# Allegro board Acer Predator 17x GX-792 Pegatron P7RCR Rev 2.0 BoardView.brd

Outline 324.5 x 193.7 mm; copper layers: TOP, GND1, IN1, GND2, IN2, GND3, VCC1, VCC2, GND4, IN3, GND5, IN4, GND6, BOTTOM. Coordinates in mm from the lower left corner of the outline.
Outline path: 0,81.74 arc(0.23,82.38) 0.82,82.72 0.83,82.72 arc(28.27,98.66) 39.1,128.49 39.1,132.99 arc(39.39,133.7) 40.1,133.99 43.1,133.99 arc(50.1,140.99) 43.1,147.99 40.1,147.99 arc(39.39,148.28) 39.1,148.99 39.1,192.7 arc(39.39,193.41) 40.1,193.7 78,193.7 arc(78.35,193.55) 78.5,193.2 arc(78.65,192.85) 79,192.7 98,192.7 arc(98.35,192.85) 98.5,193.2 arc(98.65,193.55) 99,193.7 210.2,193.7 arc(210.55,193.55) 210.7,193.2 210.7,191.9 arc(210.85,191.55) 211.2,191.4 211.5,191.4 arc(211.85,191.25) 212,190.9 212,126.77 arc(212,126.71) 212.01,126.64 arc(213.65,119.89) 216.47,113.55 arc(216.57,112.86) 216.2,112.27 214.01,110.61 arc(213.19,104.65) 219.14,103.84 221.28,105.46 arc(221.95,105.66) 222.59,105.36 arc(224.49,103.56) 226.51,101.88 arc(235.15,96.93) 244.81,94.49 arc(245.3,94.25) 245.59,93.79 246.2,91.79 arc(246.53,91.3) 247.09,91.09 arc(251.6,91.05) 256.08,91.56 arc(256.67,91.91) 256.9,92.55 256.9,94.36 arc(257.09,94.95) 257.59,95.31 arc(267.25,99.2) 275.42,105.65 arc(281.79,116.35) 284,128.6 284,135.3 arc(284.29,136.01) 285,136.3 287,136.3 arc(292,141.3) 287,146.3 285,146.3 arc(284.29,146.59) 284,147.3 284,165.9 arc(284.29,166.61) 285,166.9 293.5,166.9 arc(293.85,167.05) 294,167.4 294,167.9 arc(294.29,168.61) 295,168.9 321,168.9 arc(321.35,168.75) 321.5,168.4 321.5,158.7 arc(321.65,158.35) 322,158.2 322.15,158.2 arc(322.5,158.05) 322.65,157.7 322.65,154.7 arc(322.5,154.35) 322.15,154.2 313.85,154.2 arc(313,154.55) 313.35,153.7 313.35,138.1 arc(313,137.25) 313.85,137.6 322.15,137.6 arc(322.5,137.45) 322.65,137.1 322.65,133.1 arc(322.5,132.75) 322.15,132.6 315.04,132.6 arc(314.19,132.95) 314.54,132.1 314.54,115.8 arc(314.19,114.95) 315.04,115.3 322.15,115.3 arc(322.5,115.15) 322.65,114.8 322.65,109.15 arc(322.5,108.8) 322.15,108.65 315.75,108.65 arc(315.25,108.15) 315.75,107.65 315.75,94.05 arc(315.25,93.55) 315.75,93.05 322.15,93.05 arc(322.5,92.9) 322.65,92.55 322.65,87.35 arc(322.5,87) 322.15,86.85 321.9,86.85 arc(321.75,86.5) 321.4,86.35 315.25,86.35 arc(314.75,86.85) 314.25,86.35 314.25,72.85 arc(314.75,72.35) 315.25,72.85 321.4,72.85 arc(321.75,72.7) 321.9,72.35 321.9,59.45 arc(321.75,59.1) 321.4,58.95 315.25,58.95 arc(314.75,59.45) 314.25,58.95 314.25,45.45 arc(314.75,44.95) 315.25,45.45 321.4,45.45 arc(321.75,45.3) 321.9,44.95 321.9,40.45 arc(322.05,40.1) 322.4,39.95 324,39.95 arc(324.35,39.8) 324.5,39.45 324.5,17.9 arc(324.21,17.19) 323.5,16.9 316,16.9 arc(315.29,16.61) 315,15.9 315,12.9 arc(314.71,12.19) 314,11.9 243.5,11.9 arc(243.15,11.75) 243,11.4 243,7.3 arc(242.71,6.59) 242,6.3 179.1,6.3 arc(178.39,6.59) 178.1,7.3 178.1,7.5 arc(177.81,8.21) 177.1,8.5 162.5,8.5 arc(161.79,8.21) 161.5,7.5 161.5,1 arc(161.21,0.29) 160.5,0 67.2,0 arc(66.49,0.29) 66.2,1 66.2,7 arc(65.91,7.71) 65.2,8 55.3,8 arc(54.59,7.71) 54.3,7 54.3,5.5 arc(54.01,4.79) 53.3,4.5 1,4.5 arc(0.29,4.79) 0,5.5 0,81.74 ; 214,193.2 arc(214.15,193.55) 214.5,193.7 259.5,193.7 arc(259.85,193.55) 260,193.2 260,185.7 arc(259.85,185.35) 259.5,185.2 214.5,185.2 arc(214.15,185.35) 214,185.7 214,193.2

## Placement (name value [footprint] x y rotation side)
C0501  0.022UF/16V  [VX_C0402_SMALL]  68.31 101.84 180 top
C0502  0.022UF/16V  [VX_C0402_SMALL]  64.12 102.34 270 top
C0600  0.22UF/16V  [VX_C0402_SMALL]  128.25 117.13 180 top
C0601  0.22UF/16V  [VX_C0402_SMALL]  126.57 116.06 180 top
C0602  0.22UF/16V  [VX_C0402_SMALL]  126.57 115.17 180 top
C0603  0.22UF/16V  [VX_C0402_SMALL]  128.23 113.75 180 top
C0604  0.22UF/16V  [VX_C0402_SMALL]  126.55 113.57 180 top
C0605  0.22UF/16V  [VX_C0402_SMALL]  128.33 112.25 180 top
C0606  0.22UF/16V  [VX_C0402_SMALL]  126.6 111.13 180 top
C0607  0.22UF/16V  [VX_C0402_SMALL]  128.25 116.24 180 top
C0608  0.22UF/16V  [VX_C0402_SMALL]  128.23 114.64 180 top
C0609  0.22UF/16V  [VX_C0402_SMALL]  126.55 112.68 180 top
C0610  0.22UF/16V  [VX_C0402_SMALL]  128.33 111.36 180 top
C0611  0.22UF/16V  [VX_C0402_SMALL]  126.6 110.24 180 top
C0612  0.22UF/16V  [VX_C0402_SMALL]  128.2 108.34 180 top
C0613  0.22UF/16V  [VX_C0402_SMALL]  128.2 109.23 180 top
C0614  0.22UF/16V  [VX_C0402_SMALL]  126.55 107.3 180 top
C0615  0.22UF/16V  [VX_C0402_SMALL]  126.55 108.19 180 top
C0616  0.22UF/16V  [VX_C0402_SMALL]  126.37 106.41 180 top
C0617  0.22UF/16V  [VX_C0402_SMALL]  126.37 105.52 180 top
C0618  0.22UF/16V  [VX_C0402_SMALL]  128.56 104.35 180 top
C0619  0.22UF/16V  [VX_C0402_SMALL]  128.56 105.24 180 top
C0620  0.22UF/16V  [VX_C0402_SMALL]  126.37 104.22 180 top
C0621  0.22UF/16V  [VX_C0402_SMALL]  126.37 103.33 180 top
C0622  0.22UF/16V  [VX_C0402_SMALL]  128.05 102.29 180 top
C0623  0.22UF/16V  [VX_C0402_SMALL]  128.05 103.18 180 top
C0624  0.22UF/16V  [VX_C0402_SMALL]  126.35 102.14 180 top
C0625  0.22UF/16V  [VX_C0402_SMALL]  126.35 101.25 180 top
C0626  0.22UF/16V  [VX_C0402_SMALL]  128.05 100.16 180 top
C0627  0.22UF/16V  [VX_C0402_SMALL]  128.05 101.05 180 top
C0628  0.22UF/16V  [VX_C0402_SMALL]  126.35 100.01 180 top
C0629  0.22UF/16V  [VX_C0402_SMALL]  126.35 99.12 180 top
C0630  0.22UF/16V  [VX_C0402_SMALL]  128.05 97.9 180 top
C0631  0.22UF/16V  [VX_C0402_SMALL]  128.05 98.79 180 top
C0701  0.1UF/6.3V  [VX_C0402_SMALL]  69.56 105.42 90 bottom
C0702  0.1UF/6.3V  [VX_C0402_SMALL]  122.15 79.48 0 bottom
C0703  0.1UF/6.3V  [VX_C0402_SMALL]  147.3 27.41 270 bottom
C0900  1UF/6.3V  [VX_C0201_H14]  100.22 127.67 180 top
C0901  1UF/6.3V  [VX_C0201_H14]  97.68 112.3 180 top
C0902  1UF/6.3V  [VX_C0201_H14]  102.89 122.03 180 top
C0903  1UF/6.3V  [VX_C0201_H14]  102.89 123.55 180 top
C0904  1UF/6.3V  [VX_C0201_H14]  97.43 124.19 180 top
C0905  1UF/6.3V  [VX_C0201_H14]  100.22 122.03 0 top
C0906  1UF/6.3V  [VX_C0201_H14]  100.22 123.55 0 top
C0907  1UF/6.3V  [VX_C0201_H14]  106.32 116.09 0 top
C0908  1UF/6.3V  [VX_C0201_H14]  104.92 125.89 180 top
C0909  1UF/6.3V  [VX_C0201_H14]  104.79 112.3 180 top
C0910  1UF/6.3V  [VX_C0201_H14]  97.68 113.06 180 top
C0911  1UF/6.3V  [VX_C0201_H14]  107.97 114.15 180 top
C0912  1UF/6.3V  [VX_C0201_H14]  97.68 116.09 180 top
C0913  1UF/6.3V  [VX_C0201_H14]  107.97 113.39 180 top
C0914  1UF/6.3V  [VX_C0201_H14]  101.36 113.82 180 top
C0915  1UF/6.3V  [VX_C0201_H14]  106.19 122.79 0 top
C0916  1UF/6.3V  [VX_C0201_H14]  100.22 122.79 0 top
C0917  1UF/6.3V  [VX_C0201_H14]  102.89 124.32 180 top
C0918  1UF/6.3V  [VX_C0201_H14]  100.22 124.32 0 top
C0919  1UF/6.3V  [VX_C0201_H14]  99.84 112.3 0 top
C0920  1UF/6.3V  [VX_C0201_H14]  102.53 127.67 180 top
C0921  1UF/6.3V  [VX_C0201_H14]  97.68 113.82 180 top
C0922  1UF/6.3V  [VX_C0201_H14]  101.36 115.35 180 top
C0923  1UF/6.3V  [VX_C0201_H14]  101.36 114.59 180 top
C0924  1UF/6.3V  [VX_C0201_H14]  101.36 113.06 180 top
C0925  1UF/6.3V  [VX_C0201_H14]  103.27 113.82 0 top
C0926  1UF/6.3V  [VX_C0201_H14]  103.27 113.06 0 top
C0927  1UF/6.3V  [VX_C0201_H14]  104.79 115.35 180 top
C0928  1UF/6.3V  [VX_C0201_H14]  99.84 114.59 0 top
C0929  1UF/6.3V  [VX_C0201_H14]  97.81 125.76 180 top
C0930  1UF/6.3V  [VX_C0201_H14]  95.39 124.44 270 top
C0931  1UF/6.3V  [VX_C0201_H14]  97.43 121.9 180 top
C0932  1UF/6.3V  [VX_C0201_H14]  97.43 122.67 180 top
C0933  1UF/6.3V  [VX_C0201_H14]  106.32 113.06 0 top
C0934  1UF/6.3V  [VX_C0201_H14]  106.32 113.82 0 top
C0935  1UF/6.3V  [VX_C0201_H14]  106.32 112.3 0 top
C0936  1UF/6.3V  [VX_C0201_H14]  106.32 114.59 0 top
C0937  1UF/6.3V  [VX_C0201_H14]  99.84 115.35 0 top
C0938  1UF/6.3V  [VX_C0201_H14]  97.81 127.67 180 top
C0939  1UF/6.3V  [VX_C0201_H14]  96.16 124.44 270 top
C0940  1UF/6.3V  [VX_C0201_H14]  106.19 123.55 0 top
C0941  1UF/6.3V  [VX_C0201_H14]  106.19 124.32 0 top
C0942  1UF/6.3V  [VX_C0201_H14]  104.79 113.06 180 top
C0943  1UF/6.3V  [VX_C0201_H14]  104.79 113.82 180 top
C0944  1UF/6.3V  [VX_C0201_H14]  104.79 114.59 180 top
C0945  1UF/6.3V  [VX_C0201_H14]  102.89 122.79 180 top
C0946  1UF/6.3V  [VX_C0201_H14]  100.22 125.89 180 top
C0947  1UF/6.3V  [VX_C0201_H14]  103.27 112.3 0 top
C0948  1UF/6.3V  [VX_C0201_H14]  99.84 113.82 0 top
C0949  1UF/6.3V  [VX_C0201_H14]  99.84 113.06 0 top
C0950  1UF/6.3V  [VX_C0201_H14]  97.68 114.59 180 top
C0951  1UF/6.3V  [VX_C0201_H14]  97.68 115.35 180 top
C0952  1UF/6.3V  [VX_C0201_H14]  103.27 115.35 0 top
C0953  1UF/6.3V  [VX_C0201_H14]  103.27 114.59 0 top
C0954  1UF/6.3V  [VX_C0201_H14]  106.32 115.35 0 top
C0955  1UF/6.3V  [VX_C0201_H14]  102.53 125.89 180 top
C0956  1UF/6.3V  [VX_C0201_H14]  104.92 127.67 180 top
C0957  1UF/6.3V  [VX_C0201_H14]  97.43 123.43 180 top
C0958  1UF/6.3V  [VX_C0201_H14]  99.84 116.09 0 top
C0959  1UF/6.3V  [VX_C0201_H14]  106.19 122.03 0 top
C0960  1UF/6.3V  [VX_C0201_H14]  107.97 112.63 180 top
C0961  1UF/6.3V  [VX_C0201_H14]  107.97 114.92 180 top
C0962  1UF/6.3V  [VX_C0201_H14]  101.36 112.3 180 top
C0963  1UF/6.3V  [VX_C0201_H14]  89.04 114.43 180 top
C0964  1UF/6.3V  [VX_C0201_H14]  91.08 112.86 0 top
C0965  1UF/6.3V  [VX_C0201_H14]  93.62 112.93 0 top
C0966  1UF/6.3V  [VX_C0201_H14]  91.84 122.71 180 top
C0967  1UF/6.3V  [VX_C0201_H14]  86.25 114.41 0 top
C0968  1UF/6.3V  [VX_C0201_H14]  82.82 124.24 180 top
C0969  1UF/6.3V  [VX_C0201_H14]  87.14 121.95 180 top
C0970  1UF/6.3V  [VX_C0201_H14]  85.62 124.24 0 top
C0971  1UF/6.3V  [VX_C0201_H14]  83.46 112.81 180 top
C0972  1UF/6.3V  [VX_C0201_H14]  93.62 115.22 0 top
C0973  1UF/6.3V  [VX_C0201_H14]  85.62 120.43 0 top
C0974  1UF/6.3V  [VX_C0201_H14]  90.31 124.24 0 top
C0975  1UF/6.3V  [VX_C0201_H14]  85.62 123.48 0 top
C0976  1UF/6.3V  [VX_C0201_H14]  87.14 124.24 180 top
C0977  1UF/6.3V  [VX_C0201_H14]  93.11 125.76 0 top
C0978  1UF/6.3V  [VX_C0201_H14]  91.84 120.43 180 top
C0979  1UF/6.3V  [VX_C0201_H14]  81.3 121.19 0 top
C0980  1UF/6.3V  [VX_C0201_H14]  87.14 120.43 180 top
C0981  1UF/6.3V  [VX_C0201_H14]  83.46 114.33 180 top
C0982  1UF/6.3V  [VX_C0201_H14]  83.46 115.09 180 top
C0983  1UF/6.3V  [VX_C0201_H14]  82.82 120.43 180 top
C0984  1UF/6.3V  [VX_C0201_H14]  91.84 121.19 180 top
C0985  1UF/6.3V  [VX_C0201_H14]  90.31 120.43 0 top
C0986  1UF/6.3V  [VX_C0201_H14]  81.3 125.76 180 top
C0987  1UF/6.3V  [VX_C0201_H14]  83.71 125.76 0 top
C0988  1UF/6.3V  [VX_C0201_H14]  82.82 122.71 180 top
C0989  1UF/6.3V  [VX_C0201_H14]  82.82 121.95 180 top
C0990  1UF/6.3V  [VX_C0201_H14]  82.82 123.48 180 top
C0991  1UF/6.3V  [VX_C0201_H14]  87.14 122.71 180 top
C0992  1UF/6.3V  [VX_C0201_H14]  89.04 115.17 180 top
C0993  1UF/6.3V  [VX_C0201_H14]  91.08 113.62 0 top
C0994  1UF/6.3V  [VX_C0201_H14]  93.62 113.7 0 top
C0995  1UF/6.3V  [VX_C0201_H14]  91.84 123.48 180 top
C0996  1UF/6.3V  [VX_C0201_H14]  91.84 124.24 180 top
C0997  1UF/6.3V  [VX_C0201_H14]  81.3 124.24 0 top
C0998  1UF/6.3V  [VX_C0201_H14]  88.41 127.67 0 top
C0999  1UF/6.3V  [VX_C0201_H14]  83.71 127.67 0 top
C1000  22UF/6.3V  [VX_C0603_H39_SMALL]  121.04 104.35 0 bottom
C1001  1UF/6.3V  [VX_C0402_SMALL]  79.01 111.51 90 top
C1002  1UF/6.3V  [VX_C0402_SMALL]  80.89 110.93 0 top
C1003  4.7UF/10V  [VX_C0402_H26_SMALL]  110.38 124.36 180 top
C1004  1UF/6.3V  [VX_C0402_SMALL]  108.07 122.51 180 top
C1005  1UF/6.3V  [VX_C0402_SMALL]  108.07 121.62 180 top
C1006  4.7UF/10V  [VX_C0402_H26_SMALL]  110.38 123.48 180 top
C1007  10UF/6.3V  [VX_C0603_SMALL]  86.68 108.95 180 top
C1008  10UF/6.3V  [VX_C0603_SMALL]  105.07 103.54 270 top
C1009  10UF/6.3V  [VX_C0603_SMALL]  93.71 102.98 270 top
C1010  10UF/6.3V  [VX_C0603_SMALL]  100.22 103.54 270 top
C1011  10UF/6.3V  [VX_C0603_SMALL]  104.61 107.64 90 top
C1012  10UF/6.3V  [VX_C0603_SMALL]  99.08 107.6 90 top
C1013  10UF/6.3V  [VX_C0603_SMALL]  107.33 107.35 90 top
C1014  10UF/6.3V  [VX_C0603_SMALL]  86.25 107.43 180 top
C1015  10UF/6.3V  [VX_C0603_SMALL]  88.03 106.97 90 top
C1016  10UF/6.3V  [VX_C0603_SMALL]  109.84 105.52 270 top
C1017  1UF/6.3V  [VX_C0201_H14]  107.68 129.01 180 top
C1018  1UF/6.3V  [VX_C0201_H14]  107.68 129.78 180 top
C1019  1UF/6.3V  [VX_C0201_H14]  107.68 130.54 180 top
C1020  10UF/6.3V  [VX_C0402_H28_SMALL]  110.39 118.85 0 top
C1021  10UF/6.3V  [VX_C0402_H28_SMALL]  110.34 116.92 0 top
C1022  10UF/6.3V  [VX_C0402_H28_SMALL]  110.34 116.09 0 top
C1023  220UF/6.3V  [VX_C7343D_KEMET]  106.91 156.83 270 top
C1101  0.22UF/6.3V  [VX_C0201]  290.18 32.87 90 top
C1102  0.22UF/6.3V  [VX_C0201]  290.94 32.87 90 top
C1103  0.22UF/6.3V  [VX_C0201]  293.86 33.26 90 top
C1104  0.22UF/6.3V  [VX_C0201]  293.1 33.26 90 top
C1105  0.22UF/6.3V  [VX_C0201]  296.32 33.18 90 top
C1106  0.22UF/6.3V  [VX_C0201]  295.55 33.18 90 top
C1107  0.22UF/6.3V  [VX_C0201]  298.68 32.93 90 top
C1108  0.22UF/6.3V  [VX_C0201]  297.92 32.93 90 top
C1109  0.1UF/6.3V  [VX_C0201]  276.97 47.99 270 top
C1110  0.1UF/6.3V  [VX_C0201]  274.43 52.43 180 bottom
C1111  0.1UF/6.3V  [VX_C0201]  279.38 52.18 180 bottom
C1129  0.1UF/6.3V  [VX_C0402_SMALL]  273.67 59.09 90 top
C1130  22pF/50V  [VX_C0402_SMALL]  302.95 32.24 0 top
C1131  27PF/50V  [VX_C0402_SMALL]  300.41 32.24 180 top
C1132  0.22UF/6.3V  [VX_C0201]  303.51 39.04 0 top
C1133  0.22UF/6.3V  [VX_C0201]  303.51 38.33 0 top
C1134  0.22UF/6.3V  [VX_C0201]  303.51 36.8 0 top
C1135  0.22UF/6.3V  [VX_C0201]  303.51 37.51 0 top
C1136  0.1UF/6.3V  [VX_C0201]  286.85 38.5 0 bottom
C1137  0.1UF/6.3V  [VX_C0201]  286.85 39.21 0 bottom
C1138  0.1UF/6.3V  [VX_C0201]  284.82 44.43 0 top
C1139  0.1UF/6.3V  [VX_C0201]  284.82 43.72 0 top
C1140  0.1UF/6.3V  [VX_C0201]  285.09 42.96 0 top
C1141  0.1UF/6.3V  [VX_C0201]  285.09 42.25 0 top
C1142  0.1UF/6.3V  [VX_C0201]  285.15 41.49 0 top
C1143  0.1UF/6.3V  [VX_C0201]  285.15 40.78 0 top
C1144  0.1UF/6.3V  [VX_C0201]  285.24 39.99 0 top
C1145  0.1UF/6.3V  [VX_C0201]  285.24 39.28 0 top
C1146  0.1UF/6.3V  [VX_C0201]  286.87 40.04 0 bottom
C1147  0.1UF/6.3V  [VX_C0201]  286.87 40.75 0 bottom
C1148  1UF/6.3V  [VX_C0402_SMALL]  298.62 39.44 270 bottom
C1149  1UF/6.3V  [VX_C0402_SMALL]  298.61 41.04 90 bottom
C1150  1UF/6.3V  [VX_C0402_SMALL]  299.47 41.04 90 bottom
C1151  1UF/6.3V  [VX_C0402_SMALL]  301.97 38.37 270 bottom
C1152  1UF/6.3V  [VX_C0402_SMALL]  301.13 38.37 270 bottom
C1153  1UF/6.3V  [VX_C0402_SMALL]  302.83 38.37 270 bottom
C1154  1UF/6.3V  [VX_C0402_SMALL]  299.46 39.44 270 bottom
C1155  10UF/6.3V  [VX_C0603_SMALL]  302.49 45.7 90 top
C1156  10UF/6.3V  [VX_C0603_SMALL]  303.76 45.7 90 top
C1157  10UF/6.3V  [VX_C0603_SMALL]  305.03 45.7 90 top
C1158  10UF/6.3V  [VX_C0603_SMALL]  301.22 45.7 90 top
C1159  47uF/4V  [VX_C0805_H57_SMALL]  305.09 48.29 270 top
C1160  47uF/4V  [VX_C0805_H57_SMALL]  306.81 48.29 270 top
C1161  47uF/4V  [VX_C0805_H57_SMALL]  303.36 48.29 270 top
C1163  10UF/6.3V  [VX_C0603_SMALL]  300.13 34.06 0 bottom
C1164  10UF/6.3V  [VX_C0603_SMALL]  300.13 36.73 0 bottom
C1165  1UF/6.3V  [VX_C0201_H14]  296.16 39.89 180 bottom
C1166  1UF/6.3V  [VX_C0201_H14]  296.16 40.61 180 bottom
C1167  1UF/6.3V  [VX_C0201_H14]  293.86 42.91 180 bottom
C1168  1UF/6.3V  [VX_C0201_H14]  295.13 41.61 180 bottom
C1169  1UF/6.3V  [VX_C0201_H14]  290.56 41.76 0 bottom
C1170  1UF/6.3V  [VX_C0201_H14]  290.15 39.71 180 bottom
C1171  1UF/6.3V  [VX_C0201_H14]  291.8 41.76 180 bottom
C1172  1UF/6.3V  [VX_C0201_H14]  289.54 41.51 270 bottom
C1173  1UF/6.3V  [VX_C0201_H14]  295.13 42.35 180 bottom
C1174  1UF/6.3V  [VX_C0201_H14]  294.86 37.36 270 bottom
C1175  1UF/6.3V  [VX_C0201_H14]  294.86 40.64 90 bottom
C1176  1UF/6.3V  [VX_C0201_H14]  294.74 39.66 0 bottom
C1177  1UF/6.3V  [VX_C0201_H14]  294.75 36.02 0 bottom
C1178  1UF/6.3V  [VX_C0201_H14]  292.79 40.34 270 bottom
C1179  1UF/6.3V  [VX_C0201_H14]  293.12 41.64 0 bottom
C1180  1UF/6.3V  [VX_C0201_H14]  292.86 42.63 90 bottom
C1181  1UF/6.3V  [VX_C0201_H14]  292.92 39.1 90 bottom
C1182  1UF/6.3V  [VX_C0201_H14]  292.92 37.85 270 bottom
C1183  1UF/6.3V  [VX_C0201_H14]  294.86 38.66 270 bottom
C1184  1UF/6.3V  [VX_C0201_H14]  295.59 38.04 270 bottom
C1185  1UF/6.3V  [VX_C0201_H14]  292.08 45.19 90 bottom
C1186  1UF/6.3V  [VX_C0201_H14]  299.19 43.25 90 bottom
C1187  1UF/6.3V  [VX_C0201_H14]  294.12 40.8 90 bottom
C1188  1UF/6.3V  [VX_C0201_H14]  296.53 41.64 180 bottom
C1191  47uF/4V  [VX_C0805_H57_SMALL]  280.87 44.04 90 bottom
C1192  47uF/4V  [VX_C0805_H57_SMALL]  282.65 44.04 90 bottom
C1201  0.1UF/6.3V  [VX_C0402_SMALL]  297.08 75.52 180 top
C1202  10PF/50V  [VX_C0402_SMALL]  295.36 70.59 270 top
C1203  10UF/6.3V  [VX_C0603_SMALL]  295.38 52.99 270 top
C1204  1UF/6.3V  [VX_C0402_SMALL]  289.16 54.59 180 top
C1205  1UF/6.3V  [VX_C0402_SMALL]  296.4 52.81 270 top
C1206  10UF/6.3V  [VX_C0603_SMALL]  294.11 52.99 270 top
C1207  2.2UF/6.3V  [VX_C0603_SMALL]  298 52.41 0 top
C1208  2.2UF/6.3V  [VX_C0603_SMALL]  286.61 54.31 0 top
C1209  22UF/6.3V  [VX_C0603_H39_SMALL]  287.69 60.61 270 top
C1210  22UF/6.3V  [VX_C0603_H39_SMALL]  286.42 63.81 90 top
C1211  22UF/6.3V  [VX_C0603_H39_SMALL]  286.42 60.61 270 top
C1212  0.1UF/6.3V  [VX_C0402_SMALL]  288.78 60.61 270 top
C1217  4.7UF/6.3V  [VX_C0603_SMALL]  299.5 61.96 270 top
C1218  1UF/6.3V  [VX_C0402_SMALL]  298 62.12 90 top
C1219  0.1UF/6.3V  [VX_C0402_SMALL]  296.78 62.59 90 top
C1220  10PF/25V  [VX_C0201]  308.72 28.05 270 top
C1221  2.2UF/6.3V  [VX_C0603_SMALL]  286.61 52.81 0 top
C1222  10UF/6.3V  [VX_C0805_H57_SMALL]  307.45 28.43 270 top
C1223  220PF/50V  [VX_C0402_SMALL]  302.9 57.36 0 top
C1224  220PF/50V  [VX_C0402_SMALL]  302.44 59.42 0 top
C1225  0.47UF/6.3V  [VX_C0201]  317.73 32.32 180 bottom
C1226  0.47UF/6.3V  [VX_C0201]  317.73 34.37 180 bottom
C1227  0.47UF/6.3V  [VX_C0201]  317.73 31.6 180 bottom
C1228  0.47UF/6.3V  [VX_C0201]  317.73 33.65 180 bottom
C1229  0.22UF/6.3V  [VX_C0402_SMALL]  284.56 55.79 180 bottom
C1301  0.1UF/6.3V  [VX_C0402_SMALL]  299.83 87.87 90 bottom
C1302  10UF/6.3V  [VX_C0402_H28_SMALL]  300.72 87.87 90 bottom
C1303  0.1UF/6.3V  [VX_C0402_SMALL]  291.7 86.21 180 bottom
C1304  0.1UF/6.3V  [VX_C0402_SMALL]  291.7 85.2 180 bottom
C1305  0.1UF/6.3V  [VX_C0402_SMALL]  291.7 87.23 0 top
C1306  0.1UF/6.3V  [VX_C0402_SMALL]  291.7 82.15 0 top
C1307  0.1UF/6.3V  [VX_C0402_SMALL]  291.7 84.18 0 top
C1308  0.1UF/6.3V  [VX_C0402_SMALL]  291.7 81.13 0 top
C1309  0.1UF/6.3V  [VX_C0402_SMALL]  291.7 88.25 0 top
C1310  0.1UF/6.3V  [VX_C0402_SMALL]  291.7 80.12 0 top
C1311  0.1UF/6.3V  [VX_C0402_SMALL]  291.7 83.17 0 top
C1312  0.1UF/6.3V  [VX_C0402_SMALL]  291.7 85.2 0 top
C1313  0.1UF/6.3V  [VX_C0402_SMALL]  299.57 80.32 0 top
C1314  0.1UF/6.3V  [VX_C0402_SMALL]  287.51 85.45 0 bottom
C1315  10UF/6.3V  [VX_C0402_H28_SMALL]  295.13 87.87 90 bottom
C1316  0.1UF/6.3V  [VX_C0402_SMALL]  292.97 78.72 270 top
C1317  0.01UF/16V  [VX_C0402_SMALL]  298.56 78.72 270 top
C1318  0.1UF/6.3V  [VX_C0402_SMALL]  296.4 89.77 180 top
C1319  0.1UF/6.3V  [VX_C0402_SMALL]  294.24 78.72 270 top
C1320  0.1UF/6.3V  [VX_C0402_SMALL]  275.32 85.07 270 top
C1321  0.1UF/6.3V  [VX_C0402_SMALL]  281.16 85.58 270 top
C1322  10UF/6.3V  [VX_C0402_H28_SMALL]  293.77 87.28 90 top
C1323  10UF/6.3V  [VX_C0402_H28_SMALL]  272.8 84.84 180 top
C1324  10UF/6.3V  [VX_C0402_H28_SMALL]  272.8 85.68 180 top
C1401  0.1UF/6.3V  [VX_C0402_SMALL]  257.79 49.81 0 top
C1402  0.1UF/6.3V  [VX_C0402_SMALL]  257.79 46.13 0 top
C1403  0.1UF/6.3V  [VX_C0402_SMALL]  257.79 44.1 0 top
C1404  0.1UF/6.3V  [VX_C0402_SMALL]  257.79 43.08 0 top
C1405  0.1UF/6.3V  [VX_C0402_SMALL]  257.79 50.7 0 top
C1406  0.1UF/6.3V  [VX_C0402_SMALL]  257.79 42.07 0 top
C1407  0.1UF/6.3V  [VX_C0402_SMALL]  262.95 52.78 0 top
C1408  0.1UF/6.3V  [VX_C0402_SMALL]  262.95 53.83 0 top
C1409  0.1UF/6.3V  [VX_C0402_SMALL]  257.79 45.11 0 top
C1410  0.1UF/6.3V  [VX_C0402_SMALL]  257.79 47.1 0 top
C1411  2.2UF/6.3V  [VX_C0603_SMALL]  260.94 40.57 270 top
C1412  2.2UF/6.3V  [VX_C0603_SMALL]  259.34 51.82 90 top
C1413  0.1UF/6.3V  [VX_C0402_SMALL]  264.27 41.18 270 top
C1414  0.01UF/16V  [VX_C0402_SMALL]  259.57 41.05 90 top
C1501  0.01UF/16V  [VX_C0402_SMALL]  48.22 14.71 180 top
C1502  0.01UF/16V  [VX_C0402_SMALL]  48.22 15.96 180 top
C1503  0.01UF/16V  [VX_C0402_SMALL]  47.35 15.96 0 top
C1504  0.01UF/16V  [VX_C0402_SMALL]  35.01 11.54 180 top
C1505  0.01UF/16V  [VX_C0402_SMALL]  30.97 10.68 0 top
C1506  0.01UF/16V  [VX_C0402_SMALL]  30.97 11.92 0 top
C1507  0.01UF/16V  [VX_C0402_SMALL]  47.35 14.71 0 top
C1508  0.01UF/16V  [VX_C0402_SMALL]  47.35 12.48 0 top
C1509  0.01UF/16V  [VX_C0402_SMALL]  47.35 13.72 0 top
C1510  0.01UF/16V  [VX_C0402_SMALL]  30.97 12.81 0 top
C1511  0.01UF/16V  [VX_C0402_SMALL]  30.97 14.05 0 top
C1512  0.1UF/6.3V  [VX_C0402_SMALL]  45.19 17.25 180 bottom
C1513  0.1UF/6.3V  [VX_C0402_SMALL]  60.69 15.98 180 top
C1514  0.01UF/16V  [VX_C0402_SMALL]  30.11 10.68 180 top
C1515  0.01UF/16V  [VX_C0402_SMALL]  30.11 11.92 180 top
C1516  0.1UF/6.3V  [VX_C0402_SMALL]  45.42 15.55 90 top
C1517  0.1UF/6.3V  [VX_C0402_SMALL]  39.63 12 90 top
C1600  10PF/50V  [VX_C0402_SMALL]  104.5 69.45 180 bottom
C1601  10PF/50V  [VX_C0402_SMALL]  104.5 68.56 180 bottom
C1602  0.1UF/6.3V  [VX_C0402_SMALL]  66.86 71.46 0 bottom
C1603  0.1UF/6.3V  [VX_C0402_SMALL]  66.86 68.79 0 bottom
C1604  2.2UF/6.3V  [VX_C0402_H24_SMALL]  97.52 71.23 180 bottom
C1605  0.1UF/6.3V  [VX_C0402_SMALL]  98.79 69.58 0 bottom
C1606  10PF/50V  [VX_C0402_SMALL]  98.79 68.69 180 bottom
C1607  2.2UF/6.3V  [VX_C0402_H24_SMALL]  91.93 42.15 0 bottom
C1608  0.1UF/6.3V  [VX_C0402_SMALL]  99.42 42.15 0 bottom
C1609  10PF/50V  [VX_C0402_SMALL]  94.16 42.15 0 bottom
C1610  0.1UF/6.3V  [VX_C0402_SMALL]  79.36 69.22 180 bottom
C1612  10UF/6.3V  [VX_C0402_H28_SMALL]  85.4 70.06 0 bottom
C1613  0.1UF/6.3V  [VX_C0402_SMALL]  85.38 68.79 0 bottom
C1614  10UF/6.3V  [VX_C0402_H28_SMALL]  87.71 70.12 180 bottom
C1615  0.1UF/6.3V  [VX_C0402_SMALL]  87.54 68.79 180 bottom
C1616  10PF/50V  [VX_C0402_SMALL]  89.46 54.7 0 top
C1617  10PF/50V  [VX_C0402_SMALL]  99.16 54.7 180 top
C1618  10PF/50V  [VX_C0402_SMALL]  83.55 69.37 0 bottom
C1619  10PF/50V  [VX_C0402_SMALL]  75.16 68.73 180 bottom
C1620  10PF/50V  [VX_C0402_SMALL]  76.54 71.71 270 bottom
C1700  10PF/50V  [VX_C0402_SMALL]  114.41 51.56 0 bottom
C1701  10PF/50V  [VX_C0402_SMALL]  108.36 54.7 180 top
C1702  0.1UF/6.3V  [VX_C0402_SMALL]  66.86 70.57 0 bottom
C1703  0.1UF/6.3V  [VX_C0402_SMALL]  66.86 69.68 0 bottom
C1704  2.2UF/6.3V  [VX_C0402_H24_SMALL]  102.85 70.34 180 bottom
C1705  0.1UF/6.3V  [VX_C0402_SMALL]  102.85 68.56 0 bottom
C1706  10PF/50V  [VX_C0402_SMALL]  102.85 69.45 180 bottom
C1707  0.1UF/6.3V  [VX_C0402_SMALL]  116.68 49.07 0 top
C1708  2.2UF/6.3V  [VX_C0402_H24_SMALL]  116.68 49.94 180 top
C1709  10PF/50V  [VX_C0402_SMALL]  106.71 54.7 180 top
C1710  0.1UF/6.3V  [VX_C0402_SMALL]  59.26 68.76 270 bottom
C1712  1UF/6.3V  [VX_C0402_SMALL]  61.7 100.95 180 top
C1713  10UF/6.3V  [VX_C0402_H28_SMALL]  83.81 42.15 0 bottom
C1714  0.47UF/6.3V  [VX_C0402_SMALL]  61.7 100.06 180 top
C1715  10UF/6.3V  [VX_C0402_H28_SMALL]  61.45 103.74 180 top
C1717  10PF/50V  [VX_C0402_SMALL]  64.98 67.55 270 bottom
C1718  10PF/50V  [VX_C0402_SMALL]  80.12 42.15 0 bottom
C1719  10PF/50V  [VX_C0402_SMALL]  114.79 46.46 180 bottom
C1801  10UF/6.3V  [VX_C0402_H28_SMALL]  55.91 67.52 270 bottom
C1802  10UF/6.3V  [VX_C0402_H28_SMALL]  80.19 68 90 bottom
C1803  10UF/6.3V  [VX_C0402_H28_SMALL]  97.49 42.15 0 bottom
C1804  10UF/6.3V  [VX_C0402_H28_SMALL]  59.65 67.55 0 bottom
C1805  10UF/6.3V  [VX_C0402_H28_SMALL]  70.19 69.58 0 bottom
C1806  10UF/6.3V  [VX_C0402_H28_SMALL]  70.19 68.74 0 bottom
C1807  10UF/6.3V  [VX_C0402_H28_SMALL]  72.22 69.43 180 bottom
C1808  10UF/6.3V  [VX_C0402_H28_SMALL]  83.55 68.54 0 bottom
C1809  10UF/6.3V  [VX_C0402_H28_SMALL]  73.29 67.52 90 bottom
C1810  10UF/6.3V  [VX_C0402_H28_SMALL]  54.57 42.27 0 bottom
C1811  10UF/6.3V  [VX_C0402_H28_SMALL]  77.48 67.55 90 bottom
C1812  10UF/6.3V  [VX_C0402_H28_SMALL]  81.67 69.22 180 bottom
C1813  10UF/6.3V  [VX_C0402_H28_SMALL]  50.91 67.52 270 bottom
C1814  10UF/6.3V  [VX_C0402_H28_SMALL]  74.76 67.52 90 bottom
C1815  10UF/6.3V  [VX_C0402_H28_SMALL]  64.98 69.17 90 bottom
C1816  10UF/6.3V  [VX_C0402_H28_SMALL]  95.69 69.15 90 bottom
C1817  10UF/6.3V  [VX_C0402_H28_SMALL]  91.37 67.51 0 bottom
C1818  10UF/6.3V  [VX_C0402_H28_SMALL]  97.24 67.55 270 bottom
C1819  10UF/6.3V  [VX_C0402_H28_SMALL]  95.89 42.15 180 bottom
C1820  10UF/6.3V  [VX_C0402_H28_SMALL]  103 54.69 180 top
C1821  10UF/6.3V  [VX_C0402_H28_SMALL]  96.35 67.55 270 bottom
C1822  10UF/6.3V  [VX_C0402_H28_SMALL]  89.26 42.15 0 bottom
C1823  10UF/6.3V  [VX_C0402_H28_SMALL]  74.78 54.7 0 top
C1824  10UF/6.3V  [VX_C0402_H28_SMALL]  77.07 54.7 0 top
C1825  10UF/6.3V  [VX_C0402_H28_SMALL]  80.94 54.7 180 top
C1826  10UF/6.3V  [VX_C0402_H28_SMALL]  104.76 42.15 180 bottom
C1827  10UF/6.3V  [VX_C0402_H28_SMALL]  46.36 67.52 270 bottom
C1828  10UF/6.3V  [VX_C0402_H28_SMALL]  85.5 54.7 0 top
C1829  10UF/6.3V  [VX_C0402_H28_SMALL]  47.91 67.52 270 bottom
C1830  10UF/6.3V  [VX_C0402_H28_SMALL]  66.66 42.27 180 bottom
C1831  10UF/6.3V  [VX_C0402_H28_SMALL]  64.47 42.22 0 bottom
C1832  10UF/6.3V  [VX_C0402_H28_SMALL]  55.79 54.7 180 top
C1833  1UF/6.3V  [VX_C0402_SMALL]  50.12 54.7 180 top
C1834  1UF/6.3V  [VX_C0402_SMALL]  105.05 54.7 0 top
C1835  1UF/6.3V  [VX_C0402_SMALL]  93.69 54.7 180 top
C1836  1UF/6.3V  [VX_C0402_SMALL]  60.36 54.69 180 top
C1837  1UF/6.3V  [VX_C0402_SMALL]  44.99 54.7 180 top
C1838  1UF/6.3V  [VX_C0402_SMALL]  70.46 54.7 0 top
C1839  1UF/6.3V  [VX_C0402_SMALL]  66.83 54.7 0 top
C1840  1UF/6.3V  [VX_C0402_SMALL]  106.41 42.15 0 bottom
C1841  1UF/6.3V  [VX_C0402_SMALL]  69.96 42.27 180 bottom
C1842  1UF/6.3V  [VX_C0402_SMALL]  43.82 42.27 0 bottom
C1843  1UF/6.3V  [VX_C0402_SMALL]  52.78 54.68 0 top
C1844  1UF/6.3V  [VX_C0402_SMALL]  81.9 42.15 180 bottom
C1845  1UF/6.3V  [VX_C0402_SMALL]  62.87 42.22 180 bottom
C1846  1UF/6.3V  [VX_C0402_SMALL]  89.74 67.9 90 bottom
C1847  1UF/6.3V  [VX_C0402_SMALL]  96.98 69.17 90 bottom
C1848  1UF/6.3V  [VX_C0402_SMALL]  49.38 67.52 270 bottom
C1849  1UF/6.3V  [VX_C0402_SMALL]  52.97 42.27 180 bottom
C1850  1UF/6.3V  [VX_C0402_SMALL]  75.83 42.27 0 bottom
C1851  1UF/6.3V  [VX_C0402_SMALL]  74 42.27 180 bottom
C1852  1UF/6.3V  [VX_C0402_SMALL]  71.84 42.27 0 bottom
C1853  1UF/6.3V  [VX_C0402_SMALL]  68.36 42.27 0 bottom
C1854  1UF/6.3V  [VX_C0402_SMALL]  83.55 67.67 0 bottom
C1855  1UF/6.3V  [VX_C0402_SMALL]  71.84 68.21 90 bottom
C1856  1UF/6.3V  [VX_C0402_SMALL]  45.14 68.51 180 bottom
C1857  1UF/6.3V  [VX_C0402_SMALL]  81.08 68 90 bottom
C1858  1UF/6.3V  [VX_C0402_SMALL]  67.67 67.98 180 bottom
C1859  1UF/6.3V  [VX_C0402_SMALL]  57.51 67.52 270 bottom
C1860  1UF/6.3V  [VX_C0402_SMALL]  64.7 54.72 180 top
C1861  1UF/6.3V  [VX_C0402_SMALL]  67.67 67.14 180 bottom
C1862  1UF/6.3V  [VX_C0402_SMALL]  72.56 54.72 0 top
C1863  1UF/6.3V  [VX_C0402_SMALL]  58.15 54.72 0 top
C1864  1UF/6.3V  [VX_C0402_SMALL]  62.72 54.72 0 top
C1865  10UF/6.3V  [VX_C0402_H28_SMALL]  104.5 71.23 180 bottom
C1866  10UF/6.3V  [VX_C0402_H28_SMALL]  104.5 70.34 180 bottom
C1867  1UF/6.3V  [VX_C0402_SMALL]  104.59 72.12 180 bottom
C1868  1UF/6.3V  [VX_C0402_SMALL]  104.59 73.01 180 bottom
C1869  10UF/6.3V  [VX_C0402_H28_SMALL]  114.41 50.69 0 bottom
C1872  1UF/6.3V  [VX_C0402_SMALL]  114.41 49.85 0 bottom
C1880  1UF/6.3V  [VX_C0402_SMALL]  114 56.93 270 bottom
C1881  10UF/6.3V  [VX_C0402_H28_SMALL]  115.73 56.93 270 bottom
C1882  10UF/6.3V  [VX_C0402_H28_SMALL]  115.7 58.58 90 bottom
C1883  1UF/6.3V  [VX_C0402_SMALL]  114.87 58.58 90 bottom
C1886  10UF/6.3V  [VX_C0402_H28_SMALL]  109.96 54.69 0 top
C1888  1UF/6.3V  [VX_C0402_SMALL]  114.41 49.02 0 bottom
C1893  10UF/6.3V  [VX_C0402_H28_SMALL]  114.41 48.18 0 bottom
C1894  10UF/6.3V  [VX_C0402_H28_SMALL]  116.59 56.93 270 bottom
C1895  1UF/6.3V  [VX_C0402_SMALL]  114 58.58 90 bottom
C1896  1UF/6.3V  [VX_C0402_SMALL]  114.87 56.93 270 bottom
C1897  10UF/6.3V  [VX_C0402_H28_SMALL]  116.36 46.62 0 top
C1898  1UF/6.3V  [VX_C0402_SMALL]  116.36 45.78 0 top
C1899  10UF/6.3V  [VX_C0402_H28_SMALL]  116.36 44.94 0 top
C2000  0.22UF/6.3V  [VX_C0201]  209.84 54.36 0 bottom
C2001  0.22UF/6.3V  [VX_C0201]  209.84 55.25 0 bottom
C2002  0.1UF/6.3V  [VX_C0402_SMALL]  211.59 60.66 0 bottom
C2003  0.1UF/6.3V  [VX_C0402_SMALL]  211.59 61.48 0 bottom
C2012  0.1UF/6.3V  [VX_C0402_SMALL]  208.51 56.11 0 bottom
C2013  0.1UF/6.3V  [VX_C0402_SMALL]  208.51 57 0 bottom
C2014  0.22UF/6.3V  [VX_C0201]  207.32 53.88 0 bottom
C2015  0.22UF/6.3V  [VX_C0201]  207.32 52.99 0 bottom
C2016  0.22UF/6.3V  [VX_C0201]  209.84 52.1 0 bottom
C2017  0.22UF/6.3V  [VX_C0201]  209.84 52.99 0 bottom
C2018  0.22UF/6.3V  [VX_C0201]  207.63 50.58 0 bottom
C2019  0.22UF/6.3V  [VX_C0201]  207.63 51.46 0 bottom
C2020  0.1UF/6.3V  [VX_C0402_SMALL]  209.51 57.89 0 bottom
C2021  0.1UF/6.3V  [VX_C0402_SMALL]  209.51 58.78 0 bottom
C2200  0.1UF/6.3V  [VX_C0402_SMALL]  243.23 67.09 180 top
C2201  47PF/50V  [VX_C0402_SMALL]  228.51 74.35 90 bottom
C2202  10PF/50V  [VX_C0402_SMALL]  246.07 63.35 0 top
C2203  10PF/50V  [VX_C0402_SMALL]  247.68 62.19 0 top
C2204  10PF/50V  [VX_C0402_SMALL]  245.83 53.86 0 bottom
C2300  10PF/50V  [VX_C0402_SMALL]  244.33 77.25 90 bottom
C2301  10PF/50V  [VX_C0402_SMALL]  243.44 77.25 90 bottom
C2302  10PF/50V  [VX_C0402_SMALL]  245.22 77.25 90 bottom
C2303  10PF/50V  [VX_C0402_SMALL]  241.66 77.25 90 bottom
C2304  100PF/50V  [VX_C0402_SMALL]  237.8 43.34 90 top
C2305  100PF/50V  [VX_C0402_SMALL]  238.64 43.34 90 top
C2306  100PF/50V  [VX_C0402_SMALL]  239.48 43.34 270 top
C2307  100PF/50V  [VX_C0402_SMALL]  240.85 43.34 270 top
C2308  100PF/50V  [VX_C0402_SMALL]  235.91 43.34 90 top
C2309  100PF/50V  [VX_C0402_SMALL]  239.48 43.34 270 bottom
C2310  10PF/50V  [VX_C0402_SMALL]  242.55 77.25 90 bottom
C2311  1000PF/16V  [VX_C0201]  234.14 40.7 270 top
C2400  0.1UF/6.3V  [VX_C0402_SMALL]  239.5 71.4 270 top
C2401  0.1UF/6.3V  [VX_C0402_SMALL]  249.15 66.91 180 bottom
C2402  0.1UF/6.3V  [VX_C0402_SMALL]  246.23 69.37 270 top
C2403  0.1UF/6.3V  [VX_C0402_SMALL]  226.98 27.39 270 top
C2404  0.1UF/6.3V  [VX_C0402_SMALL]  249.92 77.12 180 bottom
C2405  0.1UF/6.3V  [VX_C0402_SMALL]  254.23 74.91 180 bottom
C2406  0.1UF/6.3V  [VX_C0402_SMALL]  254.9 71.81 90 bottom
C2500  18PF/50V  [VX_C0402_SMALL]  244.61 70.72 90 bottom
C2501  18PF/50V  [VX_C0402_SMALL]  243.77 68.51 270 bottom
C2502  27PF/50V  [VX_C0402_SMALL]  210.9 68.84 90 bottom
C2503  27PF/50V  [VX_C0402_SMALL]  210.9 67.19 270 bottom
C2600  22UF/6.3V  [VX_C0603_H39_SMALL]  230.87 58.14 0 top
C2601  22UF/6.3V  [VX_C0603_H39_SMALL]  230.87 56.93 0 top
C2602  0.1UF/6.3V  [VX_C0402_SMALL]  231.78 49.46 180 top
C2603  0.1UF/6.3V  [VX_C0402_SMALL]  238.66 48.92 270 top
C2604  0.1UF/6.3V  [VX_C0402_SMALL]  227.74 48.6 270 top
C2605  22UF/6.3V  [VX_C0603_H39_SMALL]  219.94 72.55 180 top
C2606  22UF/6.3V  [VX_C0603_H39_SMALL]  219.94 71.28 180 top
C2607  1UF/6.3V  [VX_C0402_SMALL]  220.07 70.13 180 top
C2608  22UF/6.3V  [VX_C0603_H39_SMALL]  219.28 53.83 270 top
C2609  1UF/6.3V  [VX_C0402_SMALL]  221.72 54.34 270 top
C2610  0.1UF/6.3V  [VX_C0402_SMALL]  240.39 69.4 90 top
C2611  22UF/6.3V  [VX_C0603_H39_SMALL]  246.03 76.48 90 top
C2612  22UF/6.3V  [VX_C0603_H39_SMALL]  244.76 76.48 90 top
C2613  22UF/6.3V  [VX_C0603_H39_SMALL]  210.06 47.66 180 bottom
C2614  22UF/6.3V  [VX_C0805_H55_SMALL]  213.37 48.01 90 top
C2615  1UF/6.3V  [VX_C0402_SMALL]  212.97 49.25 90 bottom
C2616  0.1UF/6.3V  [VX_C0402_SMALL]  239.91 62.44 90 top
C2617  1UF/6.3V  [VX_C0402_SMALL]  240.77 62.44 90 top
C2618  22UF/6.3V  [VX_C0603_H39_SMALL]  232.25 60.26 270 top
C2619  22UF/6.3V  [VX_C0603_H39_SMALL]  231.94 70.37 90 top
C2620  1UF/6.3V  [VX_C0402_SMALL]  230.63 72.96 90 top
C2621  1UF/6.3V  [VX_C0402_SMALL]  230.71 76.08 180 top
C2622  1UF/6.3V  [VX_C0402_SMALL]  240.7 54.17 180 top
C2623  0.1UF/6.3V  [VX_C0402_SMALL]  248.52 57.94 0 top
C2624  0.1UF/6.3V  [VX_C0402_SMALL]  238.02 59.11 0 top
C2625  1UF/6.3V  [VX_C0402_SMALL]  240.47 58.98 180 top
C2626  0.1UF/6.3V  [VX_C0402_SMALL]  247.76 73.01 270 top
C2627  0.1UF/6.3V  [VX_C0402_SMALL]  226.55 55.48 270 top
C2628  0.1UF/6.3V  [VX_C0402_SMALL]  230.91 69.47 90 top
C2629  0.1UF/6.3V  [VX_C0402_SMALL]  238.92 65.56 90 top
C2630  0.1UF/6.3V  [VX_C0402_SMALL]  249.41 59.52 180 top
C2826  1UF/6.3V  [VX_C0402_SMALL]  274.25 65.77 270 bottom
C2827  1UF/6.3V  [VX_C0402_SMALL]  273.51 63.61 270 bottom
C2828  1UF/6.3V  [VX_C0402_SMALL]  272.57 63.61 270 bottom
C3000  10UF/6.3V  [VX_C0805_H57_SMALL]  147.55 37.83 90 top
C3001  0.1UF/6.3V  [VX_C0402_SMALL]  148.81 38.4 90 top
C3002  0.1UF/6.3V  [VX_C0402_SMALL]  167.19 30.49 0 top
C3003  0.1UF/6.3V  [VX_C0402_SMALL]  144.56 26.91 180 top
C3004  0.1UF/6.3V  [VX_C0402_SMALL]  164.95 27.87 180 top
C3005  0.1UF/6.3V  [VX_C0402_SMALL]  161.86 24.19 0 bottom
C3009  0.1UF/6.3V  [VX_C0402_SMALL]  158.22 38.45 90 top
C3011  100PF/50V  [VX_C0402_SMALL]  155.72 38.45 90 top
C3015  0.1UF/6.3V  [VX_C0402_SMALL]  157.4 38.45 270 top
C3019  10UF/6.3V  [VX_C0805_H57_SMALL]  147.94 14.84 270 top
C3020  0.1UF/6.3V  [VX_C0402_SMALL]  149.71 14.71 0 top
C3021  0.1UF/6.3V  [VX_C0402_SMALL]  151.87 17.76 0 top
C3022  10PF/50V  [VX_C0402_SMALL]  156.57 38.45 90 top
C3023  10PF/50V  [VX_C0402_SMALL]  159.62 17.51 270 top
C3024  10PF/50V  [VX_C0402_SMALL]  149.64 38.4 90 top
C3025  10PF/50V  [VX_C0402_SMALL]  165.79 33.53 0 top
C3100  0.1UF/6.3V  [VX_C0402_SMALL]  176.89 25.25 270 top
C3101  1UF/6.3V  [VX_C0402_SMALL]  177.78 25.25 270 top
C3102  39PF/50V  [VX_C0402_SMALL]  209.41 24.63 0 top
C3103  39PF/50V  [VX_C0402_SMALL]  207.76 24.63 180 top
C3104  10UF/6.3V  [VX_C0603_SMALL]  277.35 51.16 180 bottom
C3105  0.1UF/6.3V  [VX_C0402_SMALL]  277.09 58.15 0 bottom
C3300  0.1UF/6.3V  [VX_C0402_SMALL]  280.24 94.6 180 top
C3301  1UF/6.3V  [VX_C0402_SMALL]  280.27 92.82 180 top
C3302  10UF/6.3V  [VX_C0603_SMALL]  280.52 91.8 180 top
C3303  0.1UF/6.3V  [VX_C0402_SMALL]  278.15 97.26 180 bottom
C3304  1UF/6.3V  [VX_C0402_SMALL]  278.15 96.37 180 bottom
C3305  4.7UF/6.3V  [VX_C0603_SMALL]  278.24 95.36 180 bottom
C3306  0.1UF/6.3V  [VX_C0402_SMALL]  280.24 95.49 0 top
C3307  1UF/6.3V  [VX_C0402_SMALL]  280.27 93.71 0 top
C3308  0.1UF/6.3V  [VX_C0402_SMALL]  275.6 97.29 0 top
C3309  10UF/6.3V  [VX_C0603_SMALL]  276.59 102.77 90 bottom
C3310  10UF/6.3V  [VX_C0603_SMALL]  283.32 99.39 90 bottom
C3311  10UF/6.3V  [VX_C0603_SMALL]  275.44 100.61 180 bottom
C3312  10UF/6.3V  [VX_C0603_SMALL]  282.91 97.25 0 bottom
C3313  0.1UF/6.3V  [VX_C0402_SMALL]  274.43 98.58 180 top
C3314  0.1UF/6.3V  [VX_C0402_SMALL]  274.43 99.47 180 top
C3315  0.1UF/6.3V  [VX_C0402_SMALL]  285.82 100.35 0 top
C3316  1UF/6.3V  [VX_C0402_SMALL]  284.59 100.08 270 top
C3317  0.1UF/6.3V  [VX_C0402_SMALL]  285.02 103.69 90 top
C3318  1UF/6.3V  [VX_C0402_SMALL]  284.13 103.69 90 top
C3319  0.1UF/6.3V  [VX_C0402_SMALL]  276.33 102.26 90 top
C3320  0.1UF/6.3V  [VX_C0402_SMALL]  280.92 104.57 90 bottom
C3321  0.1UF/6.3V  [VX_C0402_SMALL]  278.67 104.68 90 bottom
C3322  0.1UF/6.3V  [VX_C0402_SMALL]  277.73 103.03 90 bottom
C3323  1UF/6.3V  [VX_C0402_SMALL]  282.17 99.39 90 bottom
C3324  15PF/50V  [VX_C0402_SMALL]  286.75 102.52 270 top
C3325  15PF/50V  [VX_C0402_SMALL]  286.75 104.34 90 top
C3400  0.01UF/25V  [VX_C0402_SMALL]  291.78 154.89 180 top
C3401  1000PF/2KV  [VX_C1206_H75]  307.75 154.62 270 top
C3402  10PF/50V  [VX_C0402_SMALL]  298.94 153.14 0 bottom
C3403  10PF/50V  [VX_C0402_SMALL]  306.33 140.95 45 top
C3404  10PF/50V  [VX_C0402_SMALL]  307.57 139.68 45 top
C3600  2.2UF/6.3V  [VX_C0603_SMALL]  8.67 36.81 90 top
C3601  10UF/6.3V  [VX_C0603_SMALL]  9.99 36.81 90 top
C3602  10UF/6.3V  [VX_C0603_SMALL]  5.82 34.53 90 top
C3603  1UF/6.3V  [VX_C0402_SMALL]  6.89 34.91 90 top
C3604  1UF/6.3V  [VX_C0402_SMALL]  6.33 36.81 180 top
C3605  10UF/6.3V  [VX_C0603_SMALL]  11.23 36.81 90 top
C3606  0.1UF/6.3V  [VX_C0402_SMALL]  11.03 33.89 0 top
C3607  10UF/6.3V  [VX_C0402_H28_SMALL]  14.46 29.06 90 top
C3608  0.1UF/6.3V  [VX_C0402_SMALL]  2.42 18.4 180 top
C3609  10UF/6.3V  [VX_C0603_SMALL]  2.14 17.25 180 top
C3610  1UF/6.3V  [VX_C0402_SMALL]  1.89 29.83 180 top
C3611  10UF/6.3V  [VX_C0603_SMALL]  2.14 26.4 180 top
C3612  10UF/6.3V  [VX_C0603_SMALL]  3.79 35.03 90 top
C3613  10UF/6.3V  [VX_C0603_SMALL]  3.79 32.75 90 top
C3614  1UF/6.3V  [VX_C0402_SMALL]  1.89 27.54 180 top
C3615  10UF/6.3V  [VX_C0603_SMALL]  2.14 25.13 180 top
C3616  10UF/6.3V  [VX_C0805_H57_SMALL]  9.56 21.19 270 top
C3617  0.1UF/6.3V  [VX_C0402_SMALL]  15.22 24.24 0 top
C3618  100PF/50V  [VX_C0402_SMALL]  15.22 23.35 180 top
C3619  100PF/50V  [VX_C0402_SMALL]  16.87 23.86 90 bottom
C3620  100PF/50V  [VX_C0402_SMALL]  15.35 21.7 180 bottom
C3621  100PF/50V  [VX_C0402_SMALL]  14.2 20.81 0 bottom
C3622  100PF/50V  [VX_C0402_SMALL]  13.06 19.18 180 bottom
C3623  10UF/6.3V  [VX_C0805_H57_SMALL]  3.92 23.1 180 top
C3624  0.1UF/6.3V  [VX_C0402_SMALL]  4.55 24.49 180 top
C3626  22pF/50V  [VX_C0402_SMALL]  12.68 23.55 270 top
C3627  10PF/50V  [VX_C0402_SMALL]  6.66 22.08 270 top
C3628  10PF/50V  [VX_C0402_SMALL]  5.82 22.08 270 top
C3629  22pF/50V  [VX_C0402_SMALL]  8.11 23.86 90 top
C3630  0.1UF/6.3V  [VX_C0402_SMALL]  11.28 23.22 0 top
C3631  10UF/6.3V  [VX_C0805_H57_SMALL]  11.92 21.32 0 top
C3633  10UF/6.3V  [VX_C0603_SMALL]  14.97 35.03 0 top
C3639  4.7UF/6.3V  [VX_C0603_SMALL]  14.2 31.99 0 top
C3640  4.7UF/6.3V  [VX_C0603_SMALL]  14.2 30.72 0 top
C3642  10PF/50V  [VX_C0402_SMALL]  11.28 24.11 0 top
C3645  1000PF/16V  [VX_C0402_SMALL]  15.86 44.18 180 top
C3646  1000PF/16V  [VX_C0402_SMALL]  2.14 37.95 0 top
C3647  1000PF/16V  [VX_C0402_SMALL]  16.24 30.08 180 top
C3648  1UF/6.3V  [VX_C0402_SMALL]  12.68 10.01 270 top
C3649  1UF/6.3V  [VX_C0402_SMALL]  11.79 10.01 270 top
C3700  1UF/6.3V  [VX_C0402_SMALL]  66.53 13.06 180 top
C3701  10UF/6.3V  [VX_C0603_SMALL]  66.22 12.02 180 top
C3702  0.047UF/16V  [VX_C0402_SMALL]  60.94 11.92 180 bottom
C3703  0.047UF/16V  [VX_C0402_SMALL]  60.94 12.81 180 bottom
C3705  100PF/50V  [VX_C0402_SMALL]  229.22 20.43 180 top
C3706  100PF/50V  [VX_C0402_SMALL]  231.12 20.43 0 top
C3707  100PF/50V  [VX_C0402_SMALL]  232.77 20.43 180 top
C3708  100PF/50V  [VX_C0402_SMALL]  234.42 20.43 0 top
C3709  2.2UF/6.3V  [VX_C0603_SMALL]  63.1 12 0 bottom
C3711  10PF/50V  [VX_C0402_SMALL]  70.59 14.21 180 top
C4400  0.1UF/6.3V  [VX_C0402_SMALL]  142.73 8.62 0 top
C4401  0.1UF/6.3V  [VX_C0402_SMALL]  59.54 126.73 90 bottom
C4402  0.1UF/6.3V  [VX_C0402_SMALL]  54.96 126.73 90 bottom
C4403  0.1UF/6.3V  [VX_C0402_SMALL]  61.67 126.75 90 bottom
C4404  0.1UF/6.3V  [VX_C0402_SMALL]  178.54 22.59 270 bottom
C4515  2.2UF/6.3V  [VX_C0402_H24_SMALL]  111.11 190.02 180 bottom
C4516  4.7UF/6.3V  [VX_C0603_SMALL]  115.04 191.5 90 bottom
C4517  1UF/25V  [VX_C0402_H24_SMALL]  103.74 191.75 90 bottom
C4518  1UF/25V  [VX_C0402_H24_SMALL]  102.85 191.75 90 bottom
C4519  0.1UF/6.3V  [VX_C0402_SMALL]  121.77 182.15 90 bottom
C4520  0.1UF/6.3V  [VX_C0402_SMALL]  120.88 182.15 90 bottom
C4521  0.1UF/6.3V  [VX_C0402_SMALL]  123.17 182.15 90 bottom
C4522  0.1UF/6.3V  [VX_C0402_SMALL]  124.06 182.15 90 bottom
C4526  0.1UF/6.3V  [VX_C0402_SMALL]  121.01 191.12 90 bottom
C4529  0.1UF/6.3V  [VX_C0402_SMALL]  114.79 181.89 90 bottom
C4530  0.1UF/6.3V  [VX_C0402_SMALL]  113.9 181.89 90 bottom
C4531  0.1UF/6.3V  [VX_C0402_SMALL]  116.19 181.89 90 bottom
C4532  10UF/6.3V  [VX_C0603_SMALL]  112.5 191.5 90 bottom
C4533  0.1UF/6.3V  [VX_C0402_SMALL]  117.07 181.89 90 bottom
C4534  0.1UF/6.3V  [VX_C0402_SMALL]  119.36 181.89 90 bottom
C4535  0.1UF/6.3V  [VX_C0402_SMALL]  118.47 181.89 90 bottom
C4536  0.1UF/6.3V  [VX_C0402_SMALL]  109.07 188.7 180 bottom
C4538  0.1UF/6.3V  [VX_C0402_SMALL]  102.09 187.81 90 bottom
C4539  0.1UF/6.3V  [VX_C0402_SMALL]  107.42 188.45 0 bottom
C4540  10UF/6.3V  [VX_C0603_SMALL]  107.68 181.59 180 bottom
C4541  10UF/6.3V  [VX_C0603_SMALL]  107.68 182.86 180 bottom
C4542  10UF/6.3V  [VX_C0603_SMALL]  113.77 191.5 90 bottom
C4545  0.1UF/6.3V  [VX_C0402_SMALL]  107.04 191.75 90 bottom
C4546  0.1UF/6.3V  [VX_C0402_SMALL]  111.11 188.7 180 bottom
C4601  0.1UF/6.3V  [VX_C0402_SMALL]  302.04 109.07 270 top
C4602  0.1UF/6.3V  [VX_C0402_SMALL]  303.71 109.07 270 top
C4603  0.1UF/6.3V  [VX_C0402_SMALL]  302.88 109.07 270 top
C4604  0.1UF/6.3V  [VX_C0402_SMALL]  294.62 109.38 180 top
C4605  0.1UF/6.3V  [VX_C0402_SMALL]  294.62 112 180 top
C4606  0.1UF/6.3V  [VX_C0402_SMALL]  301.2 109.07 270 top
C4607  0.1UF/6.3V  [VX_C0402_SMALL]  294.62 108.54 180 top
C4608  0.1UF/6.3V  [VX_C0402_SMALL]  294.62 107.7 180 top
C4612  0.1UF/6.3V  [VX_C0402_SMALL]  294.62 113.66 180 top
C4613  0.1UF/6.3V  [VX_C0402_SMALL]  294.62 115.93 180 top
C4618  0.1UF/6.3V  [VX_C0402_SMALL]  289.67 111.59 0 top
C4619  0.1UF/6.3V  [VX_C0402_SMALL]  290.37 109.8 0 top
C4620  0.1UF/6.3V  [VX_C0402_SMALL]  289.67 110.7 0 top
C4621  0.1UF/6.3V  [VX_C0402_SMALL]  290.37 108.91 0 top
C4622  0.1UF/6.3V  [VX_C0402_SMALL]  291.59 115.09 0 top
C4623  0.1UF/6.3V  [VX_C0402_SMALL]  291.59 114.2 0 top
C4624  0.1UF/6.3V  [VX_C0402_SMALL]  289.31 113.31 0 top
C4625  0.1UF/6.3V  [VX_C0402_SMALL]  289.31 112.42 0 top
C4626  0.1UF/6.3V  [VX_C0402_SMALL]  289.03 117.41 180 top
C4627  0.1UF/6.3V  [VX_C0402_SMALL]  290.43 121.06 0 top
C4628  0.1UF/6.3V  [VX_C0402_SMALL]  308.14 126.64 0 top
C4629  0.1UF/6.3V  [VX_C0402_SMALL]  308.14 128.54 0 top
C4630  0.1UF/6.3V  [VX_C0402_SMALL]  308.14 125.82 0 top
C4631  0.1UF/6.3V  [VX_C0402_SMALL]  308.14 127.73 0 top
C4632  0.1UF/6.3V  [VX_C0402_SMALL]  308.14 124.78 0 top
C4633  0.1UF/6.3V  [VX_C0402_SMALL]  308.14 123.97 0 top
C4634  0.1UF/6.3V  [VX_C0402_SMALL]  309.41 119.7 0 top
C4635  0.1UF/6.3V  [VX_C0402_SMALL]  309.41 118.89 0 top
C4636  0.01UF/25V  [VX_C0402_SMALL]  301.48 116.69 270 top
C4637  10UF/6.3V  [VX_C0805_H57_SMALL]  296.27 105.39 270 top
C4638  0.1UF/6.3V  [VX_C0402_SMALL]  309.63 110.27 0 top
C4639  10UF/6.3V  [VX_C0603_SMALL]  309.66 109.13 0 top
C4640  0.1UF/6.3V  [VX_C0402_SMALL]  309.76 117.63 180 top
C4641  47UF/6.3V  [VX_C0805_H57_SMALL]  309.1 116.34 180 top
C4801  0.1UF/6.3V  [VX_C0402_SMALL]  307.24 83.24 0 bottom
C4806  0.1UF/6.3V  [VX_C0402_SMALL]  308.46 89.21 90 bottom
C4809  470PF/50V  [VX_C0402_SMALL]  308.31 86.21 90 top
C4810  470PF/50V  [VX_C0402_SMALL]  308.31 84.56 270 top
C4811  1PF/50V  [VX_C0402_H20_SMALL]  310.25 91.68 270 top
C5000  0.1UF/6.3V  [VX_C0402_SMALL]  288.55 133.21 90 top
C5001  0.1UF/6.3V  [VX_C0402_SMALL]  258.65 85.81 0 top
C5002  1UF/6.3V  [VX_C0402_SMALL]  139.17 39.99 270 top
C5003  0.1UF/6.3V  [VX_C0402_SMALL]  53.42 124.82 0 bottom
C5004  2200PF/50V  [VX_C0402_SMALL]  288.55 131.55 270 top
C5005  1UF/6.3V  [VX_C0402_SMALL]  43.29 119.11 180 bottom
C5006  1UF/6.3V  [VX_C0402_SMALL]  259.07 91.14 180 top
C5007  0.1UF/6.3V  [VX_C0402_SMALL]  282.74 111.48 0 bottom
C5008  0.1UF/6.3V  [VX_C0402_SMALL]  143.29 31.88 0 top
C5009  0.1UF/6.3V  [VX_C0402_SMALL]  70.47 5.19 90 top
C5106  0.1UF/6.3V  [VX_C0402_SMALL]  20.22 13.19 180 top
C5107  10UF/6.3V  [VX_C0603_SMALL]  21.82 13.57 90 top
C5116  10UF/6.3V  [VX_C0603_SMALL]  25.63 35.9 0 top
C5117  0.1UF/6.3V  [VX_C0402_SMALL]  24.36 22.21 180 top
C5118  0.1UF/6.3V  [VX_C0402_SMALL]  26.78 22.08 180 top
C5119  10PF/50V  [VX_C0402_SMALL]  26.78 21.19 0 top
C5120  0.22UF/6.3V  [VX_C0402_SMALL]  35.03 23.98 90 top
C5121  0.01UF/16V  [VX_C0402_SMALL]  17.74 29.22 0 bottom
C5122  0.01UF/16V  [VX_C0402_SMALL]  17.74 28.33 0 bottom
C5123  0.01UF/16V  [VX_C0402_SMALL]  17.89 27.41 0 bottom
C5124  0.01UF/16V  [VX_C0402_SMALL]  17.89 26.52 0 bottom
C5125  0.1UF/6.3V  [VX_C0402_SMALL]  27.16 38.72 0 top
C5126  0.1UF/6.3V  [VX_C0402_SMALL]  27.16 37.83 0 top
C5127  0.1UF/6.3V  [VX_C0402_SMALL]  26.37 36.96 0 top
C5128  0.1UF/6.3V  [VX_C0402_SMALL]  24.36 21.32 180 top
C5131  0.22UF/6.3V  [VX_C0402_SMALL]  29.04 27.41 0 bottom
C5132  0.22UF/6.3V  [VX_C0402_SMALL]  29.04 26.52 0 bottom
C5133  0.1UF/6.3V  [VX_C0402_SMALL]  35.29 38.21 180 top
C5134  0.1UF/6.3V  [VX_C0402_SMALL]  35.32 35.39 180 top
C5135  0.1UF/6.3V  [VX_C0402_SMALL]  35.32 36.28 180 top
C5136  0.1UF/6.3V  [VX_C0402_SMALL]  35.92 23.98 90 top
C5137  0.22UF/6.3V  [VX_C0402_SMALL]  35.32 34.5 180 top
C5138  0.22UF/6.3V  [VX_C0402_SMALL]  26.78 22.97 0 top
C5139  0.22UF/6.3V  [VX_C0402_SMALL]  24.36 23.1 180 top
C5147  1000PF/16V  [VX_C0402_SMALL]  20.22 12.3 180 top
C5150  0.22UF/6.3V  [VX_C0402_SMALL]  29.06 30.59 0 bottom
C5151  0.22UF/6.3V  [VX_C0402_SMALL]  29.06 29.7 0 bottom
C5154  0.22UF/6.3V  [VX_C0402_SMALL]  29.06 32.62 0 bottom
C5155  0.22UF/6.3V  [VX_C0402_SMALL]  29.06 33.51 0 bottom
C5158  0.22UF/6.3V  [VX_C0402_SMALL]  28.81 35.77 0 bottom
C5159  0.22UF/6.3V  [VX_C0402_SMALL]  28.81 34.88 0 bottom
C5160  22UF/6.3V  [VX_C0603_H39_SMALL]  23.09 13.57 90 top
C5161  22UF/6.3V  [VX_C0603_H39_SMALL]  35.31 33.41 180 top
C5162  22UF/6.3V  [VX_C0603_H39_SMALL]  30.71 26.78 0 top
C5167  10PF/50V  [VX_C0402_SMALL]  20.22 11.41 180 top
C5168  10PF/50V  [VX_C0402_SMALL]  27.16 39.61 0 top
C5169  0.01UF/16V  [VX_C0402_SMALL]  43.34 16.42 270 bottom
C5170  0.01UF/16V  [VX_C0402_SMALL]  42.48 16.42 270 bottom
C5171  0.01UF/16V  [VX_C0402_SMALL]  40.77 16.42 270 bottom
C5172  0.01UF/16V  [VX_C0402_SMALL]  41.64 16.42 270 bottom
C5173  0.1UF/6.3V  [VX_C0402_SMALL]  44.96 9.63 90 top
C5175  0.22UF/6.3V  [VX_C0402_SMALL]  38.21 9.89 90 top
C5176  22UF/6.3V  [VX_C0603_H39_SMALL]  42.17 9.51 90 top
C5177  0.22UF/6.3V  [VX_C0402_SMALL]  43.19 9.63 90 top
C5178  0.1UF/6.3V  [VX_C0402_SMALL]  36.43 9.89 90 top
C5179  0.1UF/6.3V  [VX_C0402_SMALL]  37.32 9.89 90 top
C5180  0.1UF/6.3V  [VX_C0402_SMALL]  44.08 9.63 90 top
C5181  0.1UF/6.3V  [VX_C0402_SMALL]  55.86 15.6 270 top
C5182  10PF/50V  [VX_C0402_SMALL]  35.54 9.89 90 top
C5183  10UF/6.3V  [VX_C0603_SMALL]  58.91 15.22 90 top
C5184  10PF/50V  [VX_C0402_SMALL]  45.85 9.63 90 top
C5185  0.1UF/6.3V  [VX_C0402_SMALL]  56.75 15.6 90 top
C5200  0.1UF/6.3V  [VX_C0402_SMALL]  306.05 66.4 180 top
C5201  0.1UF/6.3V  [VX_C0402_SMALL]  305.8 63.91 90 top
C5202  10PF/50V  [VX_C0402_SMALL]  306.69 63.91 90 top
C5300  10UF/6.3V  [VX_C0603_SMALL]  292.06 98.86 270 top
C5301  0.1UF/6.3V  [VX_C0402_SMALL]  293.1 99.14 270 top
C5302  1UF/6.3V  [VX_C0402_SMALL]  298.23 96.96 270 top
C5303  10PF/50V  [VX_C0402_SMALL]  289.41 98.96 270 top
C5306  0.01UF/16V  [VX_C0402_SMALL]  291.04 98.97 90 top
C5307  0.1UF/6.3V  [VX_C0402_SMALL]  290.23 98.97 270 top
C5342  100PF/25V  [VX_C0201]  225.13 40.75 270 bottom
C5347  100PF/25V  [VX_C0201]  225.89 40.75 270 bottom
C5348  100PF/25V  [VX_C0201]  301.48 102.47 90 top
C5349  100PF/25V  [VX_C0201]  300.89 96.43 270 top
C5501  0.1UF/6.3V  [VX_C0402_SMALL]  308.11 74.79 90 top
C5502  10UF/6.3V  [VX_C0603_SMALL]  308.57 44.09 270 top
C5503  0.1UF/6.3V  [VX_C0402_SMALL]  309.38 46.89 90 top
C5505  22UF/6.3V  [VX_C0603_H39_SMALL]  307.07 74.91 90 top
C5506  22UF/6.3V  [VX_C0603_H39_SMALL]  309.86 44.09 270 top
C5507  1UF/6.3V  [VX_C0402_SMALL]  304.15 68.05 180 top
C5508  0.1UF/6.3V  [VX_C0402_SMALL]  304.27 51.67 0 top
C5509  0.1UF/6.3V  [VX_C0402_SMALL]  304.27 52.56 0 top
C5510  0.1UF/6.3V  [VX_C0402_SMALL]  301.1 76.05 0 top
C5511  0.1UF/6.3V  [VX_C0402_SMALL]  301.1 77.07 0 top
C5600  0.1UF/6.3V  [VX_C0402_SMALL]  90.71 184.94 0 top
C5801  0.1UF/6.3V  [VX_C0402_SMALL]  304.07 129.78 90 top
C5802  0.1UF/6.3V  [VX_C0402_SMALL]  303.89 137.75 0 top
C5803  10UF/6.3V  [VX_C0603_SMALL]  303.89 138.84 0 top
C6001  0.1UF/6.3V  [VX_C0402_SMALL]  306.43 76.69 270 bottom
C6002  0.1UF/25V  [VX_C0402_SMALL]  9.1 68.43 270 top
C6003  0.1UF/25V  [VX_C0402_SMALL]  8.31 71.99 180 top
C6004  0.1UF/25V  [VX_C0402_SMALL]  8.31 71.05 180 top
C6005  0.1UF/25V  [VX_C0402_SMALL]  9.99 68.43 270 top
C6200  0.1UF/6.3V  [VX_C0402_SMALL]  236.54 36.84 180 top
C6201  10UF/6.3V  [VX_C0603_SMALL]  238.87 37 0 top
C6202  0.1UF/6.3V  [VX_C0402_SMALL]  233.66 36.94 0 top
C6203  0.1UF/6.3V  [VX_C0402_SMALL]  236.2 27.41 0 top
C6204  0.1UF/6.3V  [VX_C0402_SMALL]  233.41 27.29 180 top
C6205  0.1UF/6.3V  [VX_C0402_SMALL]  231.37 26.73 90 top
C6206  10UF/6.3V  [VX_C0805_H57_SMALL]  228.71 34.45 90 top
C6700  0.1UF/6.3V  [VX_C0402_SMALL]  31.48 93.33 0 bottom
C6704  100PF/50V  [VX_C0402_SMALL]  13.7 43.29 180 top
C6705  100PF/50V  [VX_C0402_SMALL]  13.7 44.18 180 top
C6707  0.1UF/6.3V  [VX_C0402_SMALL]  17.25 86.75 90 top
C6708  0.1UF/6.3V  [VX_C0402_SMALL]  22.23 46.51 180 bottom
C6709  0.1UF/6.3V  [VX_C0402_SMALL]  22.23 47.35 180 bottom
C6710  0.1UF/6.3V  [VX_C0402_SMALL]  18.84 53.09 180 bottom
C6711  0.1UF/6.3V  [VX_C0402_SMALL]  18.84 53.98 180 bottom
C6712  0.1UF/6.3V  [VX_C0402_SMALL]  20.12 85.71 0 top
C6713  0.033UF/16V  [VX_C0402_SMALL]  1.96 57.26 180 top
C6714  0.033UF/16V  [VX_C0402_SMALL]  3.08 53.23 180 top
C6715  22UF/6.3V  [VX_C0603_H39_SMALL]  9.34 49.64 0 top
C6716  22UF/6.3V  [VX_C0603_H39_SMALL]  8.71 54.59 0 top
C6717  0.1UF/6.3V  [VX_C0402_SMALL]  12.68 37.83 0 top
C7000  1UF/6.3V  [VX_C0402_SMALL]  152.1 99.6 0 top
C7001  4.7uF/16V  [VX_C0603_SMALL]  126.22 125.46 270 bottom
C7002  10uF/25V  [VX_C0805_H57_SMALL_T02]  127.11 130.41 90 bottom
C7003  1UF/6.3V  [VX_C0402_SMALL]  149.53 98.15 180 top
C7004  0.22UF/16V  [VX_C0402_SMALL]  126.8 100.26 180 bottom
C7005  0.22UF/16V  [VX_C0402_SMALL]  126.8 102.09 180 bottom
C7006  4.7uF/16V  [VX_C0603_SMALL]  135.87 89.95 180 top
C7007  1UF/6.3V  [VX_C0402_SMALL]  152.1 98.75 0 top
C7008  1UF/6.3V  [VX_C0402_SMALL]  149.53 93.9 180 top
C7009  0.22UF/16V  [VX_C0402_SMALL]  126.78 103.87 180 bottom
C7010  0.22UF/16V  [VX_C0402_SMALL]  126.78 104.76 180 bottom
C7011  1UF/6.3V  [VX_C0402_SMALL]  149.54 100.21 180 top
C7012  10uF/25V  [VX_C0805_H57_SMALL_T02]  121.52 125.58 270 bottom
C7013  1UF/6.3V  [VX_C0402_SMALL]  152.19 94.5 0 top
C7014  0.22UF/16V  [VX_C0402_SMALL]  126.8 101.15 180 bottom
C7015  0.22UF/16V  [VX_C0402_SMALL]  126.8 102.98 180 bottom
C7016  1UF/6.3V  [VX_C0402_SMALL]  152.11 97.92 0 top
C7017  1UF/6.3V  [VX_C0402_SMALL]  149.53 96 180 top
C7018  10uF/25V  [VX_C0805_H57_SMALL_T02]  131.9 80.53 180 top
C7019  4.7uF/16V  [VX_C0603_SMALL]  124.95 125.46 270 bottom
C7020  0.22UF/16V  [VX_C0402_SMALL]  125.71 107.8 180 bottom
C7021  0.22UF/16V  [VX_C0402_SMALL]  125.71 106.92 180 bottom
C7022  0.22UF/16V  [VX_C0402_SMALL]  127.74 107.93 180 bottom
C7023  0.22UF/16V  [VX_C0402_SMALL]  127.74 108.82 180 bottom
